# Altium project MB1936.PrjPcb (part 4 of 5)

## Sheet USB_PCIe.SchDoc: USB_PCIe
size A3; Date: Not used; ApprovedBy: Not used; CheckedBy: Not used; Author: Not used; CompanyName: STMicroelectronics; DrawnBy: Not used; Engineer: Not used; Organization: Not used; Address1: Not used; Address2: Not used; Address3: Not used; Address4: Not used; DocumentNumber: Not used; Revision: Not used; SheetNumber: 11; SheetTotal: 18
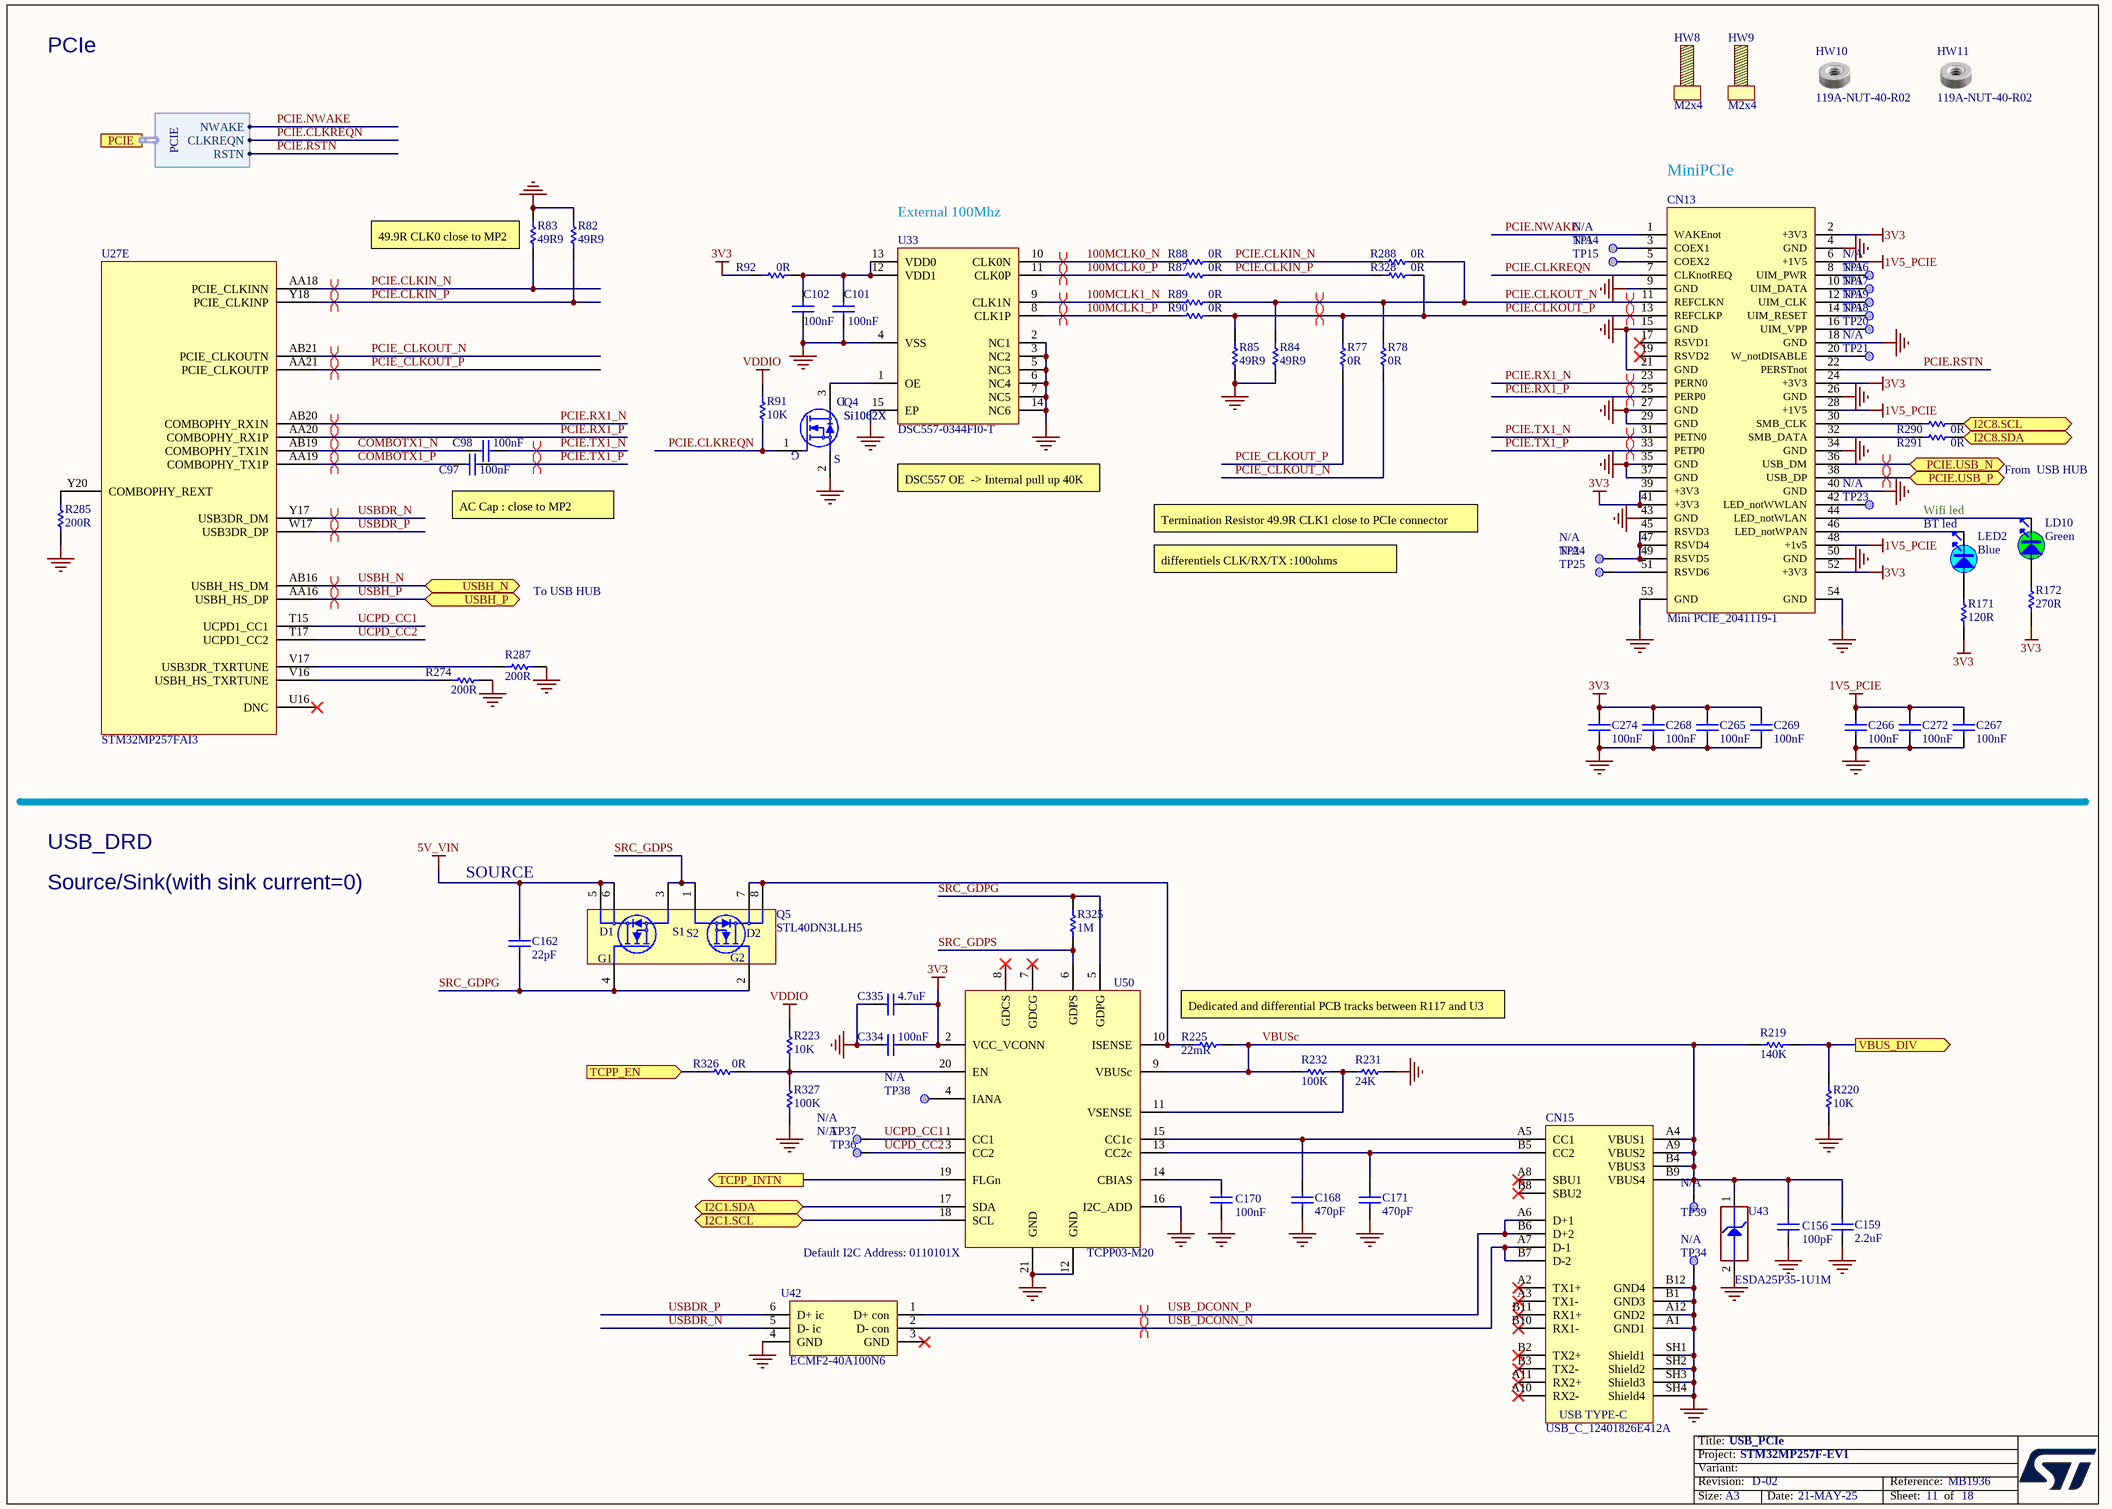
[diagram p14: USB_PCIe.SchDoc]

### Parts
C97  value 100nF  [C0201_MURATA_GRM033_H0P3]  (hidden comment: Capacitor)
C98  value 100nF  [C0201_MURATA_GRM033_H0P3]  (hidden comment: Capacitor)
C101  value 100nF  [C0402]  (hidden comment: Capacitor)
C102  value 100nF  [C0402]  (hidden comment: Capacitor)
C156  value 100pF  [C0402]  (hidden comment: Capacitor)
C159  value 2.2uF  [C0805]  (hidden comment: Capacitor)
C162  value 22pF  [C0402]  (hidden comment: Capacitor)
C168  value 470pF  [C0402]  (hidden comment: Capacitor)
C170  value 100nF  [C0603]  (hidden comment: Capacitor)
C171  value 470pF  [C0402]  (hidden comment: Capacitor)
C265  value 100nF  [C0201_H0P3]  (hidden comment: Capacitor)
C266  value 100nF  [C0201_H0P3]  (hidden comment: Capacitor)
C267  value 100nF  [C0201_H0P3]  (hidden comment: Capacitor)
C268  value 100nF  [C0201_H0P3]  (hidden comment: Capacitor)
C269  value 100nF  [C0201_H0P3]  (hidden comment: Capacitor)
C272  value 100nF  [C0201_H0P3]  (hidden comment: Capacitor)
C274  value 100nF  [C0201_H0P3]  (hidden comment: Capacitor)
C334  value 100nF  [C0402]  (hidden comment: Capacitor)
C335  value 4.7uF  [C0402]  (hidden comment: Capacitor)
CN13  value Mini PCIE_2041119-1  [CON_TE-CONNECTIVITY_2041119-1_HALF-CARD]  (hidden comment: SOCKET_Mini_PCIE)
CN15  value USB_C_12401826E412A  [CON_USB-TYPEC_AMPHENOL_12401826E412A]  (hidden comment: USB_TYPE_C_Receptacle)
HW8  value M2x4  (hidden comment: SCREW)  (mechanical)
HW9  value M2x4  (hidden comment: SCREW)  (mechanical)
HW10  value 119A-NUT-40-R02  [MISC_119A-NUT-40-R02]  (hidden comment: Standoff_mini_PCIE)  (mechanical)
HW11  value 119A-NUT-40-R02  [MISC_119A-NUT-40-R02]  (hidden comment: Standoff_mini_PCIE)  (mechanical)
LD10  value Green  [LED_0603_OSRAM_LG-Q396-PS-35_GREEN_1A2K_H0P4]  (hidden comment: LED_green)
LED2  value Blue  [LED_0603_SMD-B_BLUE_H0P4]  (hidden comment: LED_blue)
Q4  value Si1062X  Manufacturer_Part_Number: Si1062X  [MOS_SC89-3L]  (hidden comment: MOSFET_N-CHANNEL)
Q5  STL40DN3LLH5  [PowerFLAT_5x6]
R77  value 0R  [R0402]  (hidden comment: Resistor)
R78  value 0R  [R0402]  (hidden comment: Resistor)
R82  value 49R9  [R0402]  (hidden comment: Resistor)
R83  value 49R9  [R0402]  (hidden comment: Resistor)
R84  value 49R9  [R0402]  (hidden comment: Resistor)
R85  value 49R9  [R0402]  (hidden comment: Resistor)
R87  value 0R  [R0402]  (hidden comment: Resistor)
R88  value 0R  [R0402]  (hidden comment: Resistor)
R89  value 0R  [R0402]  (hidden comment: Resistor)
R90  value 0R  [R0402]  (hidden comment: Resistor)
R91  value 10K  [R0402]  (hidden comment: Resistor)
R92  value 0R  [R0402]  (hidden comment: Resistor)
R171  value 120R  [R0402]
R172  value 270R  [R0402]  (hidden comment: Resistor)
R219  value 140K  [R0402]  (hidden comment: Resistor)
R220  value 10K  [R0402]  (hidden comment: Resistor)
R223  value 10K  [R0402]  (hidden comment: Resistor)
R225  value 22mR  [R0603]  (hidden comment: Resistor)
R231  value 24K  [R0402]  (hidden comment: Resistor)
R232  value 100K  [R0402]  (hidden comment: Resistor)
R274  value 200R  [R0402]  (hidden comment: Resistor)
R285  value 200R  [R0402]  (hidden comment: Resistor)
R287  value 200R  [R0402]  (hidden comment: Resistor)
R288  value 0R  [R0402]  (hidden comment: Resistor)
R290  value 0R  [R0402]  (hidden comment: Resistor)
R291  value 0R  [R0402]  (hidden comment: Resistor)
R325  value 1M  [R0402]  (hidden comment: Resistor)
R326  value 0R  [R0402]  (hidden comment: Resistor)
R327  value 100K  [R0402]  (hidden comment: Resistor)
R328  value 0R  [R0402]  (hidden comment: Resistor)
TP14  Test Point  [TP_SMD_1MM]  (value not drawn)  (no BOM)
TP15  Test Point  [TP_SMD_1MM]  (value not drawn)  (no BOM)
TP16  Test Point  [TP_SMD_1MM]  (value not drawn)  (no BOM)
TP17  Test Point  [TP_SMD_1MM]  (value not drawn)  (no BOM)
TP18  Test Point  [TP_SMD_1MM]  (value not drawn)  (no BOM)
TP19  Test Point  [TP_SMD_1MM]  (value not drawn)  (no BOM)
TP20  Test Point  [TP_SMD_1MM]  (value not drawn)  (no BOM)
TP21  Test Point  [TP_SMD_1MM]  (value not drawn)  (no BOM)
TP23  Test Point  [TP_SMD_1MM]  (value not drawn)  (no BOM)
TP24  Test Point  [TP_SMD_1MM]  (value not drawn)  (no BOM)
TP25  Test Point  [TP_SMD_1MM]  (value not drawn)  (no BOM)
TP34  Test Point  [TP_SMD_1MM]  (value not drawn)  (no BOM)
TP36  Test Point  [TP_SMD_1MM]  (value not drawn)  (no BOM)
TP37  Test Point  [TP_SMD_1MM]  (value not drawn)  (no BOM)
TP38  Test Point  [TP_SMD_1MM]  (value not drawn)  (no BOM)
TP39  Test Point  [TP_SMD_1MM]  (value not drawn)  (no BOM)
U27  STM32MP257FAI3  [ICC_LFBGA436_18X18_P080_H1P70_STM32MP257_CODE-B0D1]  (part E of 9)
U33  DSC557-0344FI0-T  [ICC_QFN14-EPAD_3P2X2P5_P050]
U42  ECMF2-40A100N6  [ESD_UQFN-6L_1P45X1P4_P040]
U43  value ESDA25P35-1U1M  [ESD_QFN1610_2N_1K_2A]  (hidden comment: ESD-TRANSIL)
U50  TCPP03-M20  [ICC_QFN20-EPAD_4X4_P050]

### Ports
I2C1.SCL (bidir), I2C1.SDA (bidir), I2C8.SCL (bidir), I2C8.SDA (bidir), PCIE (harness PCIE), PCIE.USB_N (bidir), PCIE.USB_P (bidir), TCPP_EN (in), TCPP_INTN (out), USBH_N (bidir), USBH_P (bidir), VBUS_DIV (out)

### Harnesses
PCIE: NWAKE, CLKREQN, RSTN

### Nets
1V5_PCIE: C266.1 C267.1 C272.1 CN13.6(+1V5) CN13.28(+1V5) CN13.48(+1v5)
3V3: C265.1 C268.1 C269.2 C274.1 C334.1 C335.1 CN13.2(+3V3) CN13.24(+3V3) CN13.39(+3V3) CN13.41(+3V3) CN13.52(+3V3) R92.1 R171.2 R172.1 U50.2(VCC_VCONN)
5V_VIN: C162.2 Q5.5(D1) Q5.6(D1)
GND: C101.1 C102.1 C156.1 C159.1 C168.1 C170.1 C171.1 C265.2 C266.2 C267.2 C268.2 C269.1 C272.2 C274.2 C334.2 C335.2 CN13.4(GND) CN13.9(GND) CN13.15(GND) CN13.18(GND) CN13.21(GND) CN13.26(GND) CN13.27(GND) CN13.29(GND) CN13.34(GND) CN13.35(GND) CN13.37(GND) CN13.40(GND) CN13.43(GND) CN13.50(GND) CN13.53(GND) CN13.54(GND) CN15.A1(GND1) CN15.A12(GND2) CN15.B1(GND3) CN15.B12(GND4) CN15.SH1(Shield1) CN15.SH2(Shield2) CN15.SH3(Shield3) CN15.SH4(Shield4) Q4.2(S) R82.2 R83.2 R84.1 R85.1 R220.1 R231.2 R274.2 R285.1 R287.2 R327.1 TP34.1 U33.2(NC1) U33.3(NC2) U33.4(VSS) U33.5(NC3) U33.6(NC4) U33.7(NC5) U33.14(NC6) U33.15(EP) U42.4(GND) U43.2(GND) U50.12(GND) U50.16(I2C_ADD) U50.21(GND)
VDDIO: R91.2 R223.2
100MCLK0_N: R88.1 U33.10(CLK0N)
100MCLK0_P: R87.1 U33.11(CLK0P)
100MCLK1_N: R89.1 U33.9(CLK1N)
100MCLK1_P: R90.1 U33.8(CLK1P)
COMBOTX1_N: C98.1 U27.AB19(COMBOPHY_TX1N)
COMBOTX1_P: C97.1 U27.AA19(COMBOPHY_TX1P)
EXP_GPIO2: R291.2 ; port I2C8.SDA
EXP_GPIO3: R290.2 ; port I2C8.SCL
I2C1.SCL: U50.18(SCL) ; port I2C1.SCL
I2C1.SDA: U50.17(SDA) ; port I2C1.SDA
PCIE.CLKIN_N: R83.1 R88.2 R288.2 U27.AA18(PCIE_CLKINN)
PCIE.CLKIN_P: R82.1 R87.2 R328.2 U27.Y18(PCIE_CLKINP)
PCIE.CLKOUT_N: CN13.11(REFCLKN) R78.2 R84.2 R89.2 R288.1
PCIE.CLKOUT_P: CN13.13(REFCLKP) R77.2 R85.2 R90.2 R328.1
PCIE.CLKREQN: CN13.7(CLKnotREQ) Q4.1(G) R91.1 ; port PCIE.CLKREQN
PCIE.NWAKE: CN13.1(WAKEnot) ; port PCIE.NWAKE
PCIE.RSTN: CN13.22(PERSTnot) ; port PCIE.RSTN
PCIE.RX1_N: CN13.23(PERN0) U27.AB20(COMBOPHY_RX1N)
PCIE.RX1_P: CN13.25(PERP0) U27.AA20(COMBOPHY_RX1P)
PCIE.TX1_N: C98.2 CN13.31(PETN0)
PCIE.TX1_P: C97.2 CN13.33(PETP0)
PCIE.USB_N: CN13.36(USB_DM) ; port PCIE.USB_N
PCIE.USB_P: CN13.38(USB_DP) ; port PCIE.USB_P
PCIE_CLKOUT_N: R78.1 U27.AB21(PCIE_CLKOUTN)
PCIE_CLKOUT_P: R77.1 U27.AA21(PCIE_CLKOUTP)
SRC_GDPG: C162.1 Q5.2(G2) Q5.4(G1) R325.2 U50.5(GDPG)
SRC_GDPS: Q5.1(S2) Q5.3(S1) R325.1 U50.6(GDPS)
TCPP_EN: R326.1 ; port TCPP_EN
TCPP_INTN: U50.19(FLGn) ; port TCPP_INTN
UCPD_CC1: TP37.1 U27.T15(UCPD1_CC1) U50.1(CC1)
UCPD_CC2: TP36.1 U27.T17(UCPD1_CC2) U50.3(CC2)
USB_DCONN_N: CN15.A7(D-1) CN15.B7(D-2) U42.2(D-_con)
USB_DCONN_P: CN15.A6(D+1) CN15.B6(D+2) U42.1(D+_con)
USBDR_N: U27.Y17(USB3DR_DM) U42.5(D-_ic)
USBDR_P: U27.W17(USB3DR_DP) U42.6(D+_ic)
USBH_N: U27.AB16(USBH_HS_DM) ; port USBH_N
USBH_P: U27.AA16(USBH_HS_DP) ; port USBH_P
VBUS_DIV: R219.1 R220.2 ; port VBUS_DIV
VBUSc: C156.2 C159.2 CN15.A4(VBUS1) CN15.A9(VBUS2) CN15.B4(VBUS3) CN15.B9(VBUS4) R219.2 R225.1 R232.1 TP39.1 U43.1(IO1) U50.9(VBUSc)
NetC101_2: C101.2 C102.2 R92.2 U33.12(VDD1) U33.13(VDD0)
NetC168_2: C168.2 CN15.A5(CC1) U50.15(CC1c)
NetC170_2: C170.2 U50.14(CBIAS)
NetC171_2: C171.2 CN15.B5(CC2) U50.13(CC2c)
NetCN13_3: CN13.3(COEX1) TP14.1
NetCN13_5: CN13.5(COEX2) TP15.1
NetCN13_8: CN13.8(UIM_PWR) TP16.1
NetCN13_10: CN13.10(UIM_DATA) TP17.1
NetCN13_12: CN13.12(UIM_CLK) TP19.1
NetCN13_14: CN13.14(UIM_RESET) TP18.1
NetCN13_16: CN13.16(UIM_VPP) TP20.1
NetCN13_20: CN13.20(W_notDISABLE) TP21.1
NetCN13_30: CN13.30(SMB_CLK) R290.1
NetCN13_32: CN13.32(SMB_DATA) R291.1
NetCN13_42: CN13.42(LED_notWWLAN) TP23.1
NetCN13_44: CN13.44(LED_notWLAN) LD10.2
NetCN13_45: CN13.45(RSVD3) CN13.47(RSVD4) CN13.49(RSVD5) TP24.1
NetCN13_46: CN13.46(LED_notWPAN) LED2.2
NetCN13_51: CN13.51(RSVD6) TP25.1
NetLD10_1: LD10.1 R172.2
NetLED2_1: LED2.1 R171.1
NetQ4_3: Q4.3(D) U33.1(OE)
NetQ5_7: Q5.7(D2) Q5.8(D2) R225.2 U50.10(ISENSE)
NetR223_1: R223.1 R326.2 R327.2 U50.20(EN)
NetR231_1: R231.1 R232.2 U50.11(VSENSE)
NetR274_1: R274.1 U27.V16(USBH_HS_TXRTUNE)
NetR285_2: R285.2 U27.Y20(COMBOPHY_REXT)
NetR287_1: R287.1 U27.V17(USB3DR_TXRTUNE)
NetTP38_1: TP38.1 U50.4(IANA)

Not connected (* = marked no-connect by the designer): CN13 17(RSVD1)* 19(RSVD2)*; CN15 A2(TX1+)* A3(TX1-)* A8(SBU1)* A10(RX2-)* A11(RX2+)* B2(TX2+)* B3(TX2-)* B8(SBU2)* B10(RX1-)* B11(RX1+)*; U27 U16(DNC)*; U42 3(GND)*; U50 7(GDCG)* 8(GDCS)*

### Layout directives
differential pair: 100MCLK0_N, 100MCLK0_P, 100MCLK1_N, 100MCLK1_P, COMBOTX1_N, COMBOTX1_P, PCIE.CLKIN_N, PCIE.CLKIN_P, PCIE.CLKOUT_N, PCIE.CLKOUT_P, PCIE.RX1_N, PCIE.RX1_P, PCIE.TX1_N, PCIE.TX1_P, PCIE.USB_N, PCIE.USB_P, PCIE_CLKOUT_N, PCIE_CLKOUT_P, USB_DCONN_N, USB_DCONN_P, USBDR_N, USBDR_P, USBH_N, USBH_P

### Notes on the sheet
- PCIe
- MiniPCIe
- (near R83) 49.9R CLK0 close to MP2
- (near U33) External 100Mhz
- AC Cap : close to MP2
- DSC557 OE  -> Internal pull up 40K
- (near LED2) Wifi led
- From  USB HUB
- differentiels CLK/RX/TX :100ohms
- Termination Resistor 49.9R CLK1 close to PCIe connector
- (near LED2) BT led
- To USB HUB
- USB_DRD
- Source/Sink(with sink current=0)
- SOURCE
- Dedicated and differential PCB tracks between R117 and U3 pin 9 and 10
- (near U50) Default I2C Address: 0110101X

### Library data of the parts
C97 C98 = MCD-01535: Capacitor, MLCC,100nF, 10V, X7R, +/-10%, 0201, T=0.3mm; Part_Preference: Recommended; Manufacturer: MURATA; Manufacturer_Part_Number: GRM033R61A104KE15; Order_Code_RS: 790-2742; Component_Country_Of_Origin: Japan°°; ID: 3635; ShowFields: YES
C101 C102 C334 = MCD-00006: Capacitor, MLCC, 100nF, 16V, X7R, +/-10%, 0402, T=0.5mm; Part_Preference: Recommended; Manufacturer: YAGEO; Manufacturer_Part_Number: CC0402KRX7R7BB104; Partial_Alternate_Internal_Part_Number: MCD-03299; Order_Code_RS: 9402047; Component_Country_Of_Origin: China; ID: 2474; ShowFields: YES
C156 = MCD-00205: Capacitor, MLCC, 100pF, 50V, NPO, +/-5%, 0402, T=0.5mm; Manufacturer_Part_Number: CC0402JRNPO9BN101; Manufacturer: YAGEO; Part_Preference: Recommended; Component_Country_Of_Origin: China; ID: 2658; ShowFields: YES
C159 = MCD-02372: Capacitor, MLCC, 2.2uF, 25V, X7R, +/-10%, 0805, T=1,25mm; Part_Preference: Recommended; Manufacturer: MURATA; Manufacturer_Part_Number: GRM21BR71E225KE11; Partial_Alternate_Internal_Part_Number: MCD-04185; Component_Country_Of_Origin: Japan°; ID: 4478; ShowFields: YES
C162 = MCD-01995: Capacitor, MLCC, 22pF, 50V, C0G, +/-5%, 0402, T=0.5mm; Part_Preference: Recommended; Manufacturer: TDK; Manufacturer_Part_Number: C1005NP01H220J050BA; Partial_Alternate_Internal_Part_Number: MCD-04601; Component_Country_Of_Origin: Unknown; ID: 4095; ShowFields: YES
C168 C171 = MCD-00724: Capacitor, MLCC, 470pF, 50V, NPO, +/-5%, 0402, T=0.5mm; Manufacturer_Part_Number: CC0402JRNPO9BN471; Manufacturer: YAGEO; Part_Preference: Recommended; Component_Country_Of_Origin: China; Order_Code_RS: 199-2186; ID: 3023; ShowFields: YES
C170 = MCD-01099: Capacitor, MLCC, 100nF, 50V, X7R, +/-10%, 0603, T=0.8mm; BMS_Part_Number: 9142278; Part_Preference: Recommended; Manufacturer: YAGEO; Manufacturer_Part_Number: CC0603KRX7R9BB104; Order_Code_RS: 669-8767; Component_Country_Of_Origin: China; ID: 3397; ShowFields: YES
C265-C269 C272 C274 = MCD-00697: Capacitor, MLCC, 100nF,10V, X5R, +/-10%, 0201, T=0.3mm; Manufacturer_Part_Number: C0603X5R1A104K030BC; Manufacturer: TDK; Part_Preference: Recommended; Component_Country_Of_Origin: Unknown; ID: 3046; ShowFields: YES
C335 = MCD-01356: Capacitor, MLCC, 4.7uF, 6V3, X5R, +/-20%, 0402, T=0.5mm; Part_Preference: Recommended; Manufacturer: MURATA; Manufacturer_Part_Number: GRM155R60J475ME47; Partial_Alternate_Internal_Part_Number: MCD-04455; Order_Code_RS: 814-5230; Component_Country_Of_Origin: Japan°°; ID: 3456; ShowFields: YES
CN13 = MCD-02227: Socket_Mini PCIE, 52 pins, RA, SMD, T=4mm; Part_Type: Connector; Part_Preference: Recommended; Manufacturer: TE CONNECTIVITY; Manufacturer_Part_Number: 2041119-1; Order_Code_RS: 186-5008; Component_Country_Of_Origin: China; ShowFields: YES; ID: 4327
CN15 = MCD-03232: USB_TypeC, 24 pins, RA, SMD, T=2.96mm; Part_Type: Connector; Part_Preference: Recommended; Manufacturer: AMPHENOL CS; Manufacturer_Part_Number: 12401826E412A; Component_Country_Of_Origin: China°; ShowFields: YES; ID: 5348
HW8 HW9 = MCD-02934: Screw , M2*4 mm; Part_Type: Accessory; Part_Preference: Recommended; Manufacturer: RS PRO; Manufacturer_Part_Number: 914-1462; ShowFields: YES; ID: 5050; Component_Country_Of_Origin: Vietnam
HW10 HW11 = MCD-03022: MiniPCIe Stand off , 1.6mm; Part_Type: Mechanical; Part_Preference: Recommended; Manufacturer: ATTEND; ShowFields: YES; ID: 5138; Component_Country_Of_Origin: Taiwan
LD10 = MCD-02901: LED, Green, 2V, 20mA, 0603; Part_Type: Display; Part_Preference: Recommended; Manufacturer: EVERLIGHT; Manufacturer_Part_Number: 19-217/G7C-AN1P2/6T; Partial_Alternate_Internal_Part_Number: MCD-02400, MCD-00588; Component_Country_Of_Origin: China; ShowFields: YES; ID: 5017
LED2 = MCD-02786: LED, Blue, 2.5V to 3.1V, 10mA, 0603; Part_Type: Display; Part_Preference: Recommended; Manufacturer: EVERLIGHT; Manufacturer_Part_Number: 19-217/BHC-ZL1M2RY/6T; Full_Alternate_Internal_Part_Number: MCD-01131; Component_Country_Of_Origin: China; ShowFields: YES; ID: 4898
Q4 = MCD-02221: MOSFET N-CH 20V SC-89; Part_Preference: Recommended; Part_Type: Transistor; Manufacturer: VISHAY; Order_Code_RS: 812-3044; Component_Country_Of_Origin: Philippines; ID: 4321; ShowFields: YES
Q5 = MCD-02152: MOSFET, Dual N-channel 30 V, 0.016 Ω typ., 40 A, STripFET™ H5 Power MOSFET; Part_Preference: Recommended; Part_Type: Transistor; Manufacturer: STMICROELECTRONICS; Manufacturer_HQ_COO: EU; Component_Country_Of_Origin: China; ID: 4252; ShowFields: YES
R77 R78 R87-R90 R92 = MCD-00052: Resistor, 0R, 0402, +/-5%, 1/16W; Part_Preference: Recommended; Manufacturer: YAGEO; Manufacturer_Part_Number: RC0402JR-070RL; Order_Code_RS: 9232516RL; Component_Country_Of_Origin: China; ID: 2540; ShowFields: YES
R82-R85 = MCD-00565: Resistor, 49R9, 0402, +/-1%, 1/16W; Part_Preference: Recommended; Manufacturer: YAGEO; Manufacturer_Part_Number: RC0402FR-0749R9L; Component_Country_Of_Origin: China; ID: 3178; ShowFields: YES
R91 R220 R223 = MCD-00053: Resistor, 10K, 0402, +/-1%, 1/16W; BMS_Part_Number: 9131590; Part_Preference: Recommended; Manufacturer: YAGEO; Manufacturer_Part_Number: RC0402FR-0710KL; Order_Code_RS: 9239359; Component_Country_Of_Origin: China; ID: 2539; ShowFields: YES
R171 = MCD-00194: Resistor,120R,0402,1%,1/16W; Manufacturer_Part_Number: RC0402FR-07120RL; Manufacturer: YAGEO; Part_Preference: Recommended; Provided_By: SUBCO; ECCN_US: EAR99; ECCN_EU: NEC; Component_Country_Of_Origin: China; ID: 2674; ShowFields: YES
R172 = MCD-00441: Resistor,270R,0402,1%,1/16W; Manufacturer_Part_Number: RC0402FR-07270RL; Manufacturer: YAGEO; Part_Preference: Recommended; Provided_By: SUBCO; ECCN_US: EAR99; ECCN_EU: NEC; Component_Country_Of_Origin: China; ID: 2838; ShowFields: YES
R219 = MCD-02335: Resistor, 140K, 0402, +/-1%, 1/16W; Part_Preference: Recommended; Manufacturer: YAGEO; Manufacturer_Part_Number: RC0402FR-07140KL; Component_Country_Of_Origin: China; ID: 4441; ShowFields: YES
R225 = MCD-02232: Resistor, 22mR, 0603, +/-1%, 1/3W; Part_Preference: Recommended; Manufacturer: PANASONIC; Manufacturer_Part_Number: ERJ-3BWFR022V; Order_Code_RS: 763-8671P; Component_Country_Of_Origin: Japan; ID: 4332; ShowFields: YES
R231 = MCD-00435: Resistor, 24K, 0402, +/-1%, 1/16W; Part_Preference: Recommended; Manufacturer: YAGEO; Manufacturer_Part_Number: RC0402FR-0724KL; Component_Country_Of_Origin: China; ShowFields: YES; ID: 2845
R232 R327 = MCD-02265: Resistor,100K,0402,0.5%,1/16W; Part_Preference: Recommended; Manufacturer: YAGEO; Manufacturer_Part_Number: RC0402DR-07100KL; Component_Country_Of_Origin: China; ShowFields: YES; ID: 4365
R274 R285 R287 = MCD-00417: Resistor, 200R, 0402, +/-1%, 1/16W; Part_Preference: Recommended; Manufacturer: YAGEO; Manufacturer_Part_Number: RC0402FR-07200RL; Component_Country_Of_Origin: China; ID: 2860; ShowFields: YES
R288 R328 = MCD-00052: Resistor,0R,0402,5%,1/16W; Part_Preference: Recommended; Manufacturer: YAGEO; Manufacturer_Part_Number: RC0402JR-070RL; Order_Code_RS: 9232516RL; Component_Country_Of_Origin: China; ID: 2540; ShowFields: YES
R290 R291 = MCD-00052: Resistor, 0R, 0402, +/-5%, 1/16W; Part_Preference: Recommended; Manufacturer: YAGEO; Manufacturer_Part_Number: RC0402JR-070RL; Order_Code_RS: 9232516RL; Component_Country_Of_Origin: China; ShowFields: YES; ID: 2540
R325 = MCD-00182: Resistor, 1M, 0402, +/-1%, 1/16W; BMS_Part_Number: 9131778; Part_Preference: Recommended; Manufacturer: YAGEO; Manufacturer_Part_Number: RC0402FR-071ML; Order_Code_RS: 618-6194; Component_Country_Of_Origin: China; ShowFields: YES; ID: 2686
R326 = MCD-00052: Resistor,0R,0402,5%,1/16W; Manufacturer_Part_Number: RC0402JR-070RL; Manufacturer: YAGEO; Part_Preference: Recommended; Order_Code_RS: 9232516RL; Component_Country_Of_Origin: China; ID: 2540; ShowFields: YES
TP14-TP21 TP23-TP25 TP34 TP36-TP39 = MCD-00074: Test Point 1mm; Part_Type: Misc; Part_Preference: Recommended; Component_Country_Of_Origin: Unknown; ID: 2518; ShowFields: YES
U27 = MCD-02000: MPU, ARM Cortex-A35 + M33 32-bit MPU, 808KB RAM, With Crypto; Part_Type: IC; Part_Preference: Recommended; Manufacturer: STMICROELECTRONICS; Manufacturer_HQ_COO: EU; Component_Country_Of_Origin: Unknown; ShowFields: YES; ID: 4100
U33 = MCD-02349: Crystal-less Two Output PCIe Gen1/2/3 Clock Generator 100Mhz , 2.25V to 3.6V, 100ppm; Part_Type: IC; Part_Preference: Recommended; Manufacturer: MICROCHIP; Component_Country_Of_Origin: Unknown; ID: 4455; ShowFields: YES
U42 = MCD-03060: ESD protection & Common Filter High Speed serial Interfaces , 0.4 pitch; Part_Type: IC; Part_Preference: Recommended; Manufacturer: STMICROELECTRONICS; ShowFields: YES; ID: 5176; Component_Country_Of_Origin: China
U43 = MCD-01207: High power Transient voltage suppressor:25V/35A EOS and ESD transients protection.; BMS_Part_Number: 9179045; Part_Type: Diode; Part_Preference: Recommended; Manufacturer: STMICROELECTRONICS; Manufacturer_HQ_COO: EU; Component_Country_Of_Origin: China; Order_Code_RS: 163-9774; ID: 3289; ShowFields: YES
U50 = MCD-02130: USB Type-C Port Protection for USB DRP Power Delivery, PPS compliant; Part_Preference: Recommended; Part_Type: IC; Manufacturer: STMICROELECTRONICS; Manufacturer_HQ_COO: EU; Component_Country_Of_Origin: China; ID: 4230; ShowFields: YES

## Sheet STLINK_V3EC.SchDoc: STLINK-V3EC
size A3; Date: Not used; ApprovedBy: Not used; CheckedBy: Not used; Author: Not used; CompanyName: STMicroelectronics; DrawnBy: Not used; Engineer: Not used; Organization: Not used; Address1: Not used; Address2: Not used; Address3: Not used; Address4: Not used; DocumentNumber: Not used; Revision: V0.1; SheetNumber: 18; SheetTotal: 18
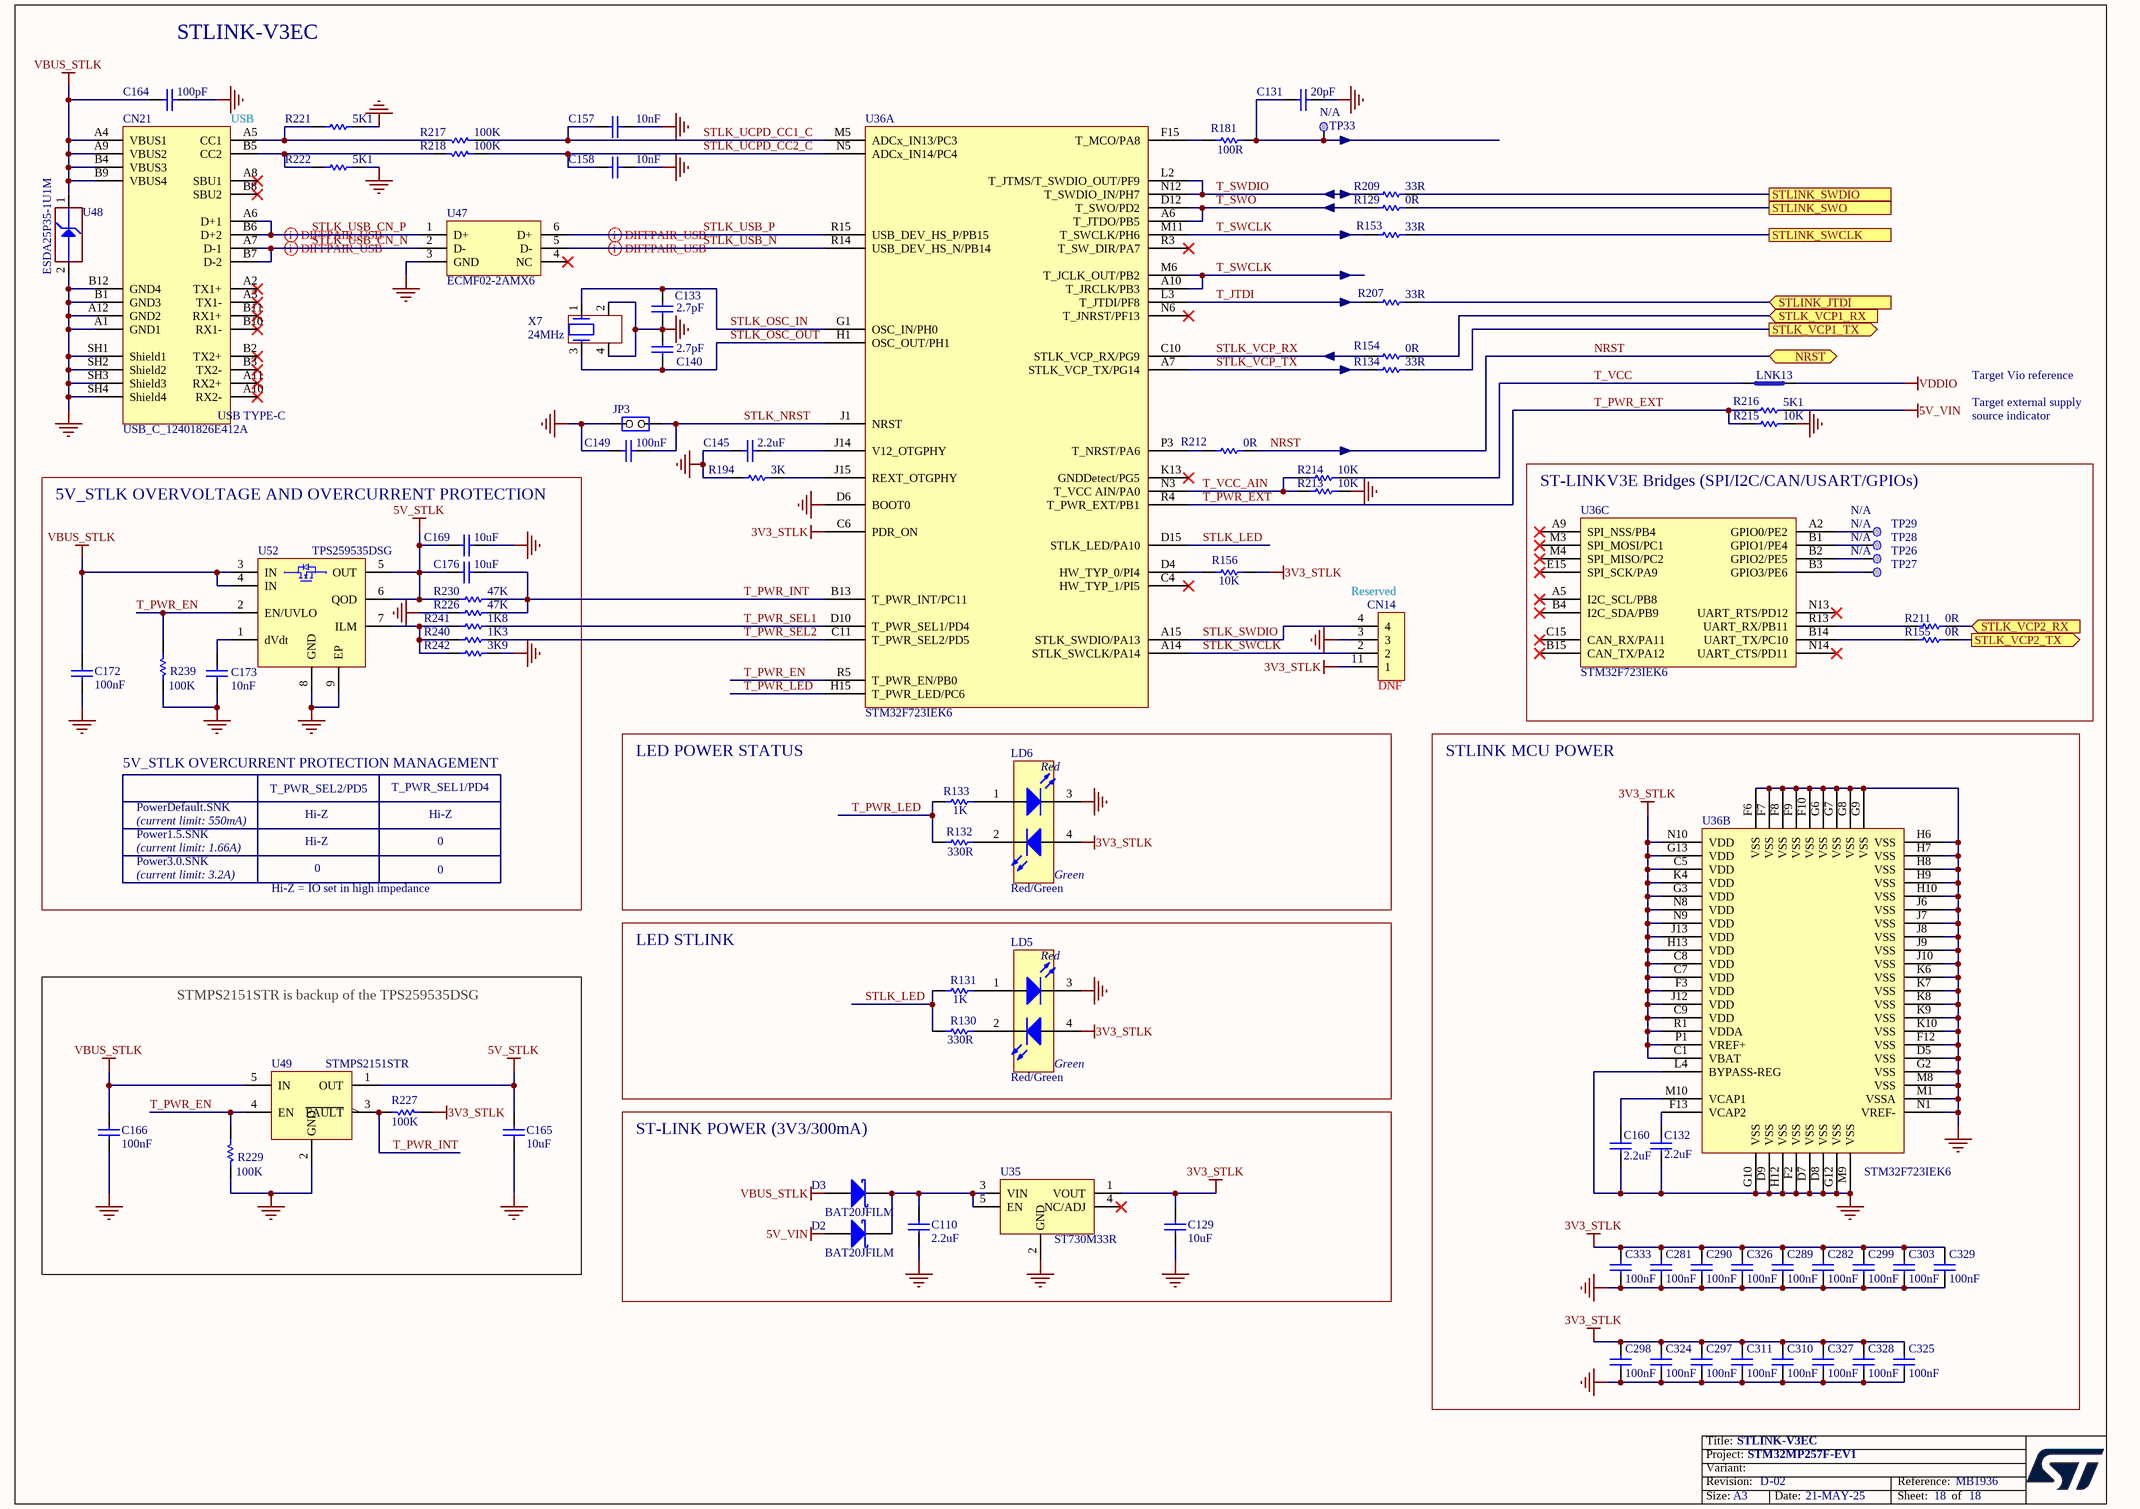
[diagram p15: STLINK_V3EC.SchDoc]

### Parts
C110  value 2.2uF  [C0805]  (hidden comment: Capacitor)
C129  value 10uF  [C0603]  (hidden comment: Capacitor)
C131  value 20pF  [C0402]  (hidden comment: Capacitor)
C132  value 2.2uF  [C0402]  (hidden comment: Capacitor)
C133  value 2.7pF  [C0402]  (hidden comment: Capacitor)
C140  value 2.7pF  [C0402]  (hidden comment: Capacitor)
C145  value 2.2uF  [C0402]  (hidden comment: Capacitor)
C149  value 100nF  [C0402]  (hidden comment: Capacitor)
C157  value 10nF  [C0402]  (hidden comment: Capacitor)
C158  value 10nF  [C0402]  (hidden comment: Capacitor)
C160  value 2.2uF  [C0402]  (hidden comment: Capacitor)
C164  value 100pF  [C0402]  (hidden comment: Capacitor)
C165  value 10uF  [C0603]  (hidden comment: Capacitor)
C166  value 100nF  [C0402]  (hidden comment: Capacitor)
C169  value 10uF  [C0603]  (hidden comment: Capacitor)
C172  value 100nF  [C0402]  (hidden comment: Capacitor)
C173  value 10nF  [C0402]  (hidden comment: Capacitor)
C176  value 10uF  [C0402]  (hidden comment: Capacitor)
C281  value 100nF  [C0402]  (hidden comment: Capacitor)
C282  value 100nF  [C0402]  (hidden comment: Capacitor)
C289  value 100nF  [C0402]  (hidden comment: Capacitor)
C290  value 100nF  [C0402]  (hidden comment: Capacitor)
C297  value 100nF  [C0402]  (hidden comment: Capacitor)
C298  value 100nF  [C0402]  (hidden comment: Capacitor)
C299  value 100nF  [C0402]  (hidden comment: Capacitor)
C303  value 100nF  [C0402]  (hidden comment: Capacitor)
C310  value 100nF  [C0402]  (hidden comment: Capacitor)
C311  value 100nF  [C0402]  (hidden comment: Capacitor)
C324  value 100nF  [C0402]  (hidden comment: Capacitor)
C325  value 100nF  [C0402]  (hidden comment: Capacitor)
C326  value 100nF  [C0402]  (hidden comment: Capacitor)
C327  value 100nF  [C0402]  (hidden comment: Capacitor)
C328  value 100nF  [C0402]  (hidden comment: Capacitor)
C329  value 100nF  [C0402]  (hidden comment: Capacitor)
C333  value 100nF  [C0402]  (hidden comment: Capacitor)
CN14  Header 4x1  [CON_SAMTEC_TSW-104-07-G-S]  (value not drawn)
CN21  value USB_C_12401826E412A  [CON_USB-TYPEC_AMPHENOL_12401826E412A]  (hidden comment: USB_TYPE_C_Receptacle)
D2  value BAT20JFILM  [DIO_SOD323_1A_2K]  (hidden comment: SCHOTTKY_1A_2K)
D3  value BAT20JFILM  [DIO_SOD323_1A_2K]  (hidden comment: SCHOTTKY_1A_2K)
JP3  Jumper_Header 2x1  [CON_SAMTEC_TSW-102-07-G-S]  (value not drawn)
LD5  value Red/Green  [LED_BI-GR_WE-150141SV73110]  (hidden comment: LED_BICOLOR)
LD6  value Red/Green  [LED_BI-GR_WE-150141SV73110]  (hidden comment: LED_BICOLOR)
LNK13  link_200  [LINK200]  (value not drawn)  (no BOM)
R129  value 0R  [R0402]  (hidden comment: Resistor)
R130  value 330R  [R0402]  (hidden comment: Resistor)
R131  value 1K  [R0402]  (hidden comment: Resistor)
R132  value 330R  [R0402]  (hidden comment: Resistor)
R133  value 1K  [R0402]  (hidden comment: Resistor)
R134  value 33R  [R0402]  (hidden comment: Resistor)
R153  value 33R  [R0402]  (hidden comment: Resistor)
R154  value 0R  [R0402]  (hidden comment: Resistor)
R155  value 0R  [R0402]  (hidden comment: Resistor)
R156  value 10K  [R0402]  (hidden comment: Resistor)
R181  value 100R  [R0402]  (hidden comment: Resistor)
R194  value 3K  [R0402]  (hidden comment: Resistor)
R207  value 33R  [R0402]  (hidden comment: Resistor)
R209  value 33R  [R0402]  (hidden comment: Resistor)
R211  value 0R  [R0402]  (hidden comment: Resistor)
R212  value 0R  [R0402]  (hidden comment: Resistor)
R213  value 10K  [R0402]  (hidden comment: Resistor)
R214  value 10K  [R0402]  (hidden comment: Resistor)
R215  value 10K  [R0402]  (hidden comment: Resistor)
R216  value 5K1  [R0402]  (hidden comment: Resistor)
R217  value 100K  [R0402]  (hidden comment: Resistor)
R218  value 100K  [R0402]  (hidden comment: Resistor)
R221  value 5K1  [R0402]  (hidden comment: Resistor)
R222  value 5K1  [R0402]  (hidden comment: Resistor)
R226  value 47K  [R0402]  (hidden comment: Resistor)
R227  value 100K  [R0402]  (hidden comment: Resistor)
R229  value 100K  [R0402]  (hidden comment: Resistor)
R230  value 47K  [R0402]  (hidden comment: Resistor)
R239  value 100K  [R0402]  (hidden comment: Resistor)
R240  value 1K3  [R0402]  (hidden comment: Resistor)
R241  value 1K8  [R0402]  (hidden comment: Resistor)
R242  value 3K9  [R0402]  (hidden comment: Resistor)
TP26  Test Point  [TP_SMD_1MM]  (value not drawn)  (no BOM)
TP27  Test Point  [TP_SMD_1MM]  (value not drawn)  (no BOM)
TP28  Test Point  [TP_SMD_1MM]  (value not drawn)  (no BOM)
TP29  Test Point  [TP_SMD_1MM]  (value not drawn)  (no BOM)
TP33  Test Point  [TP_SMD_1MM]  (value not drawn)  (no BOM)
U35  ST730M33R  [ICC_SOT23-5L_H1P45]
U36  value STM32F723IEK6  [ICC_UFBGA201_176+25_10X10_P065]  (hidden comment: STLINK-V3EC)  (parts A,B,C of 3)
U47  value ECMF02-2AMX6  [ESD_QFN-6L_1P7X1P5_P050]  (hidden comment: ​)
U48  value ESDA25P35-1U1M  [ESD_QFN1610_2N_1K_2A]  (hidden comment: ESD-TRANSIL)
U49  STMPS2151STR  [MOS_SOT23-5L]
U52  TPS259535DSG  [ICC_WSON8-EPAD_2X2_P050]
X7  value 24MHz  [CRY_NX2016SA_4P]  (hidden comment: XTAL_4_PINS)

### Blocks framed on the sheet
5V_STLK OVERVOLTAGE AND OVERCURRENT PROTECTION: C169 C172 C173 C176 R226 R230 R239-R242 U52
ST-LINKV3E Bridges (SPI/I2C/CAN/USART/GPIOs): R155 R211 TP26-TP29 U36
LED POWER STATUS: LD6 R132 R133
STLINK MCU POWER: C132 C160 C281 C282 C289 C290 C297-C299 C303 C310 C311 C324-C329 C333 U36
LED STLINK: LD5 R130 R131
STMPS2151STR is backup of the TPS259535DSG: C165 C166 R227 R229 U49
ST-LINK POWER (3V3/300mA): C110 C129 D2 D3 U35

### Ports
NRST (bidir), STLINK_JTDI (in), STLINK_SWCLK, STLINK_SWDIO, STLINK_SWO, STLK_VCP1_RX (in), STLK_VCP1_TX (out), STLK_VCP2_RX (in), STLK_VCP2_TX (out)

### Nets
3V3_STLK: C129.2 C281.1 C282.1 C289.1 C290.1 C297.1 C298.1 C299.1 C303.1 C310.1 C311.1 C324.1 C325.1 C326.1 C327.1 C328.1 C329.1 C333.1 CN14.1 LD5.4(Green_anode) LD6.4(Green_anode) R156.2 R227.1 U35.1(VOUT) U36.C1(VBAT) U36.C5(VDD) U36.C6(PDR_ON) U36.C7(VDD) U36.C8(VDD) U36.C9(VDD) U36.F3(VDD) U36.G3(VDD) U36.G13(VDD) U36.H13(VDD) U36.J12(VDD) U36.J13(VDD) U36.K4(VDD) U36.N8(VDD) U36.N9(VDD) U36.N10(VDD) U36.P1(VREF+) U36.R1(VDDA)
5V_STLK: C165.2 C169.2 C176.1 R230.1 U49.1(OUT) U52.5(OUT) U52.6(QOD)
5V_VIN: D2.1(A) R216.2
GND: C110.1 C129.1 C131.1 C132.1 C133.2 C140.1 C145.1 C149.1 C157.2 C158.2 C160.1 C164.2 C165.1 C166.1 C169.1 C172.1 C173.1 C281.2 C282.2 C289.2 C290.2 C297.2 C298.2 C299.2 C303.2 C310.2 C311.2 C324.2 C325.2 C326.2 C327.2 C328.2 C329.2 C333.2 CN14.3 CN21.A1(GND1) CN21.A12(GND2) CN21.B1(GND3) CN21.B12(GND4) CN21.SH1(Shield1) CN21.SH2(Shield2) CN21.SH3(Shield3) CN21.SH4(Shield4) JP3.2(NO) LD5.3(RED_cathode) LD6.3(RED_cathode) R194.2 R213.2 R215.2 R221.2 R222.2 R226.2 R229.1 R239.1 R242.2 U35.2(GND) U36.D5(VSS) U36.D6(BOOT0) U36.D7(VSS) U36.D8(VSS) U36.D9(VSS) U36.F2(VSS) U36.F6(VSS) U36.F7(VSS) U36.F8(VSS) U36.F9(VSS) U36.F10(VSS) U36.F12(VSS) U36.G2(VSS) U36.G6(VSS) U36.G7(VSS) U36.G8(VSS) U36.G9(VSS) U36.G10(VSS) U36.G12(VSS) U36.H6(VSS) U36.H7(VSS) U36.H8(VSS) U36.H9(VSS) U36.H10(VSS) U36.H12(VSS) U36.J6(VSS) U36.J7(VSS) U36.J8(VSS) U36.J9(VSS) U36.J10(VSS) U36.K6(VSS) U36.K7(VSS) U36.K8(VSS) U36.K9(VSS) U36.K10(VSS) U36.L4(BYPASS-REG) U36.M1(VSSA) U36.M8(VSS) U36.M9(VSS) U36.N1(VREF-) U47.3(GND) U48.2(GND) U49.2(GND) U52.8(GND) U52.9(EP) X7.2 X7.4
VBUS_STLK: C164.1 C166.2 C172.2 CN21.A4(VBUS1) CN21.A9(VBUS2) CN21.B4(VBUS3) CN21.B9(VBUS4) D3.1(A) U48.1(IO1) U49.5(IN) U52.3(IN) U52.4(IN)
VDDIO: LNK13.1
JTCK_SWCLK: R153.2 ; port STLINK_SWCLK
JTDI: R207.2 ; port STLINK_JTDI
JTDO_SWDO: R129.2 ; port STLINK_SWO
JTMS_SWDIO: R209.2 ; port STLINK_SWDIO
NRST: R212.2 ; port NRST
STLK_LED: R130.1 R131.2 U36.D15(STLK_LED/PA10)
STLK_NRST: C149.2 JP3.1(COMMON) U36.J1(NRST)
STLK_OSC_IN: C133.1 U36.G1(OSC_IN/PH0) X7.1
STLK_OSC_OUT: C140.2 U36.H1(OSC_OUT/PH1) X7.3
STLK_SWCLK: CN14.2 U36.A14(STLK_SWCLK/PA14)
STLK_SWDIO: CN14.4 U36.A15(STLK_SWDIO/PA13)
STLK_UCPD_CC1_C: C157.1 R217.1 U36.M5(ADCx_IN13/PC3)
STLK_UCPD_CC2_C: C158.1 R218.1 U36.N5(ADCx_IN14/PC4)
STLK_USB_CN_N: CN21.A7(D-1) CN21.B7(D-2) U47.2(D-)
STLK_USB_CN_P: CN21.A6(D+1) CN21.B6(D+2) U47.1(D+)
STLK_USB_N: U36.R14(USB_DEV_HS_N/PB14) U47.5(D-)
STLK_USB_P: U36.R15(USB_DEV_HS_P/PB15) U47.6(D+)
STLK_VCP1_RX: R154.2 ; port STLK_VCP1_RX
STLK_VCP1_TX: R134.2 ; port STLK_VCP1_TX
STLK_VCP2_RX: R211.1 ; port STLK_VCP2_RX
STLK_VCP2_TX: R155.1 ; port STLK_VCP2_TX
STLK_VCP_RX: R154.1 U36.C10(STLK_VCP_RX/PG9)
STLK_VCP_TX: R134.1 U36.A7(STLK_VCP_TX/PG14)
T_JTDI: R207.1 U36.L3(T_JTDI/PF8)
T_PWR_EN: R229.2 R239.2 U36.R5(T_PWR_EN/PB0) U49.4(EN) U52.2(EN/UVLO)
T_PWR_EXT: R215.1 R216.1 U36.R4(T_PWR_EXT/PB1)
T_PWR_INT: C176.2 R226.1 R227.2 R230.2 U36.B13(T_PWR_INT/PC11) U49.3(~{FAULT})
T_PWR_LED: R132.2 R133.2 U36.H15(T_PWR_LED/PC6)
T_PWR_SEL1: R241.2 U36.D10(T_PWR_SEL1/PD4)
T_PWR_SEL2: R240.2 U36.C11(T_PWR_SEL2/PD5)
T_SWCLK: R153.1 U36.A10(T_JRCLK/PB3) U36.M6(T_JCLK_OUT/PB2) U36.M11(T_SWCLK/PH6)
T_SWDIO: R209.1 U36.L2(T_JTMS/T_SWDIO_OUT/PF9) U36.N12(T_SWDIO_IN/PH7)
T_SWO: R129.1 U36.A6(T_JTDO/PB5) U36.D12(T_SWO/PD2)
T_VCC: LNK13.2 R214.2
T_VCC_AIN: R213.1 R214.1 U36.N3(T_VCC_AIN/PA0)
NetC110_2: C110.2 D2.2(K) D3.2(K) U35.3(VIN) U35.5(EN)
NetC131_2: C131.2 R181.2 TP33.1
NetC132_2: C132.2 U36.F13(VCAP2)
NetC145_2: C145.2 U36.J14(V12_OTGPHY)
NetC160_2: C160.2 U36.M10(VCAP1)
NetC173_2: C173.2 U52.1(dVdt)
NetCN21_A5: CN21.A5(CC1) R217.2 R221.1
NetCN21_B5: CN21.B5(CC2) R218.2 R222.1
NetLD5_1: LD5.1(Red_anode) R131.1
NetLD5_2: LD5.2(Green_cathode) R130.2
NetLD6_1: LD6.1(Red_anode) R133.1
NetLD6_2: LD6.2(Green_cathode) R132.1
NetR155_2: R155.2 U36.B14(UART_TX/PC10)
NetR156_1: R156.1 U36.D4(HW_TYP_0/PI4)
NetR181_1: R181.1 U36.F15(T_MCO/PA8)
NetR194_1: R194.1 U36.J15(REXT_OTGPHY)
NetR211_2: R211.2 U36.R13(UART_RX/PB11)
NetR212_1: R212.1 U36.P3(T_NRST/PA6)
NetR240_1: R240.1 R241.1 R242.1 U52.7(ILM)
NetTP26_1: TP26.1 U36.B2(GPIO2/PE5)
NetTP27_1: TP27.1 U36.B3(GPIO3/PE6)
NetTP28_1: TP28.1 U36.B1(GPIO1/PE4)
NetTP29_1: TP29.1 U36.A2(GPIO0/PE2)

Not connected (* = marked no-connect by the designer): CN21 A2(TX1+)* A3(TX1-)* A8(SBU1)* A10(RX2-)* A11(RX2+)* B2(TX2+)* B3(TX2-)* B8(SBU2)* B10(RX1-)* B11(RX1+)*; U35 4(NC/ADJ)*; U36 A5(I2C_SCL/PB8)* A9(SPI_NSS/PB4)* B4(I2C_SDA/PB9)* B15(CAN_TX/PA12)* C4(HW_TYP_1/PI5)* C15(CAN_RX/PA11)* E15(SPI_SCK/PA9)* K13(GNDDetect/PG5)* M3(SPI_MOSI/PC1)* M4(SPI_MISO/PC2)* N6(T_JNRST/PF13)* N13(UART_RTS/PD12)* N14(UART_CTS/PD11)* R3(T_SW_DIR/PA7)*; U47 4(NC)*

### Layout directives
differential pair; rule Impedance Constraint [Min = 85.00    Max = 95.00    ]: STLK_USB_CN_N, STLK_USB_CN_P, STLK_USB_N, STLK_USB_P

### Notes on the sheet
- STLINK-V3EC
- (near CN21) USB
- Target Vio reference
- Target external supply
- source indicator
- (near CN14) Reserved
- (near CN14) 1
- (near CN14) DNF
- 5V_STLK OVERCURRENT PROTECTION MANAGEMENT
- (current limit: 550mA)
- (current limit: 1.66A)
- Power1.5.SNK
- PowerDefault.SNK
- T_PWR_SEL2/PD5
- Hi-Z
- T_PWR_SEL1/PD4
- 0
- (current limit: 3.2A)
- Power3.0.SNK
- Hi-Z = IO set in high impedance

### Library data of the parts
C110 = MCD-02372: Capacitor, MLCC, 2.2uF, 25V, X7R, +/-10%, 0805, T=1,25mm; Manufacturer_Part_Number: GRM21BR71E225KE11; Manufacturer: MURATA; Part_Preference: Recommended; Partial_Alternate_Internal_Part_Number: MCD-04185; Component_Country_Of_Origin: Japan°; ShowFields: YES; ID: 4478
C129 C169 = MCD-00099: Capacitor, MLCC, 10uF, 10V, X5R, +/-10%, 0603, T=0.8mm; Part_Preference: Recommended; Manufacturer: MURATA; Manufacturer_Part_Number: GRM188R61A106KE69; Partial_Alternate_Internal_Part_Number: MCD-03152; Order_Code_RS: 2494233; Component_Country_Of_Origin: Japan°°; ShowFields: YES; ID: 2770
C131 = MCD-00016: Capacitor, MLCC, 20pF, 50V, NPO, +/- 5%, 0402, T=0.5mm; Manufacturer_Part_Number: CC0402JRNPO9BN200; Manufacturer: YAGEO; Part_Preference: Recommended; Component_Country_Of_Origin: China; ShowFields: YES; ID: 2479
C132 C145 C160 = MCD-02606: Capacitor, MLCC, 2.2uF, 6.3V, X5R, +/-10%, 0402, T=0.5mm; Part_Preference: Recommended; Manufacturer: YAGEO; Manufacturer_Part_Number: CC0402KRX5R5BB225; Order_Code_RS: 1992205; ShowFields: YES; ID: 4712; Component_Country_Of_Origin: China°
C133 C140 = MCD-01774: Capacitor, MLCC, 2.7pF, 50V, NPO, +/-0.1pF, 0402, T=0.5mm; Part_Preference: Recommended; Manufacturer: YAGEO; Manufacturer_Part_Number: CC0402BRNPO9BN2R7; Component_Country_Of_Origin: China; ID: 3874; ShowFields: YES
C149 C281 C282 C289 C290 C297-C299 C303 C310 C311 C324-C329 C333 = MCD-00006: Capacitor, MLCC, 100nF, 16V, X7R, +/-10%, 0402, T=0.5mm; Manufacturer_Part_Number: CC0402KRX7R7BB104; Manufacturer: YAGEO; Part_Preference: Recommended; Partial_Alternate_Internal_Part_Number: MCD-03299; Order_Code_RS: 9402047; Component_Country_Of_Origin: China; ShowFields: YES; ID: 2474
C157 C158 C173 = MCD-02198: Capacitor, MLCC, 10nF, 50V, X7R, +/-10%, 0402, T=0.5mm; Part_Preference: Recommended; Manufacturer: YAGEO; Manufacturer_Part_Number: CC0402KRX7R9BB103; Order_Code_RS: 6169644; Component_Country_Of_Origin: China; ShowFields: YES; ID: 4298
C164 = MCD-00205: Capacitor, MLCC, 100pF, 50V, NPO, +/-5%, 0402, T=0.5mm; Part_Preference: Recommended; Manufacturer: YAGEO; Manufacturer_Part_Number: CC0402JRNPO9BN101; Component_Country_Of_Origin: China; ShowFields: YES; ID: 2658
C165 = MCD-00099: Capacitor, MLCC, 10uF, 10V, X5R, +/-10%, 0603, T=0.8mm; Part_Preference: Recommended; Manufacturer: MURATA; Manufacturer_Part_Number: GRM188R61A106KE69; Partial_Alternate_Internal_Part_Number: MCD-03152; Order_Code_RS: 2494233; Component_Country_Of_Origin: Japan°°; ID: 2770; ShowFields: YES
C166 C172 = MCD-02355: Capacitor, MLCC, 100nF, 25V, X7R, +/-10%, 0402, T=0.5mm; Part_Preference: Recommended; Manufacturer: WALSIN TECHNOLOGY CORPORATION; Manufacturer_Part_Number: 0402B104K250CT; Partial_Alternate_Internal_Part_Number: MCD-03302, MCD-03304; Order_Code_RS: 176-3114; Component_Country_Of_Origin: Unknown; ShowFields: YES; ID: 4461
C176 = MCD-03140: Capacitor, MLCC, 10uF, 6.3V, X5R, +/-20%, 0402, T=0.5mm; Part_Preference: Recommended; Manufacturer: MURATA; Manufacturer_Part_Number: GRM155R60J106ME05; Component_Country_Of_Origin: China, Japan; ShowFields: YES; ID: 5256
CN14 = MCD-00029: Header, 4x1, 2.54mm, VR, TH, T=5.84mm/2.54mm; Manufacturer_Part_Number: TSW-104-07-G-S; Manufacturer: SAMTEC; Part_Type: Connector; Part_Preference: Recommended; Partial_Alternate_Internal_Part_Number: MCD-04227; Order_Code_RS: 161-2460; Component_Country_Of_Origin: United States°; ShowFields: YES; ID: 2487
CN21 = MCD-03232: as CN15 on sheet USB_PCIe
D2 D3 = MCD-03011: Signal Schottky Diode, If=1A, Ifsm=5A, Vf =0.54V@1A, Vrrm=23V, Ir = 0.65µA@5V, SOD-323; Part_Preference: Recommended; Manufacturer: STMICROELECTRONICS; Order_Code_RS: 165-7545; ShowFields: YES; ID: 5127; Component_Country_Of_Origin: China
JP3 = MCD-00045: Header, 2x1, 2.54mm, VR, TH, T=5.84mm/2.54mm; Part_Preference: Recommended; Part_Type: Connector; Manufacturer: SAMTEC; Manufacturer_Part_Number: TSW-102-07-G-S; Alternate_Internal_Part_Number: MCD-02390; Partial_Alternate_Internal_Part_Number: MCD-02957, MCD-03720, MCD-03979, MCD-04249; Order_Code_RS: 2505044; Component_Country_Of_Origin: China, Costa Rica, Malaysia, USA, Vietnam; ShowFields: YES; ID: 2545
LD5 LD6 = MCD-02631: LED Bicolor, Green/Red, 2V, 20mA,  4-PLCC; Part_Type: Display; Part_Preference: Recommended; Manufacturer: WURTH ELEKTRONIK; Manufacturer_Part_Number: 150141SV73110; Partial_Alternate_Internal_Part_Number: MCD-02402; Order_Code_RS: 184-6963; Component_Country_Of_Origin: China; ShowFields: YES; ID: 4737
LNK13 = MCD-02777: Track link on PCB 200um width for layout routing. No component assembly and no component in BOM; Part_Type: Misc; Part_Preference: Recommended; ShowFields: YES; ID: 4889; Component_Country_Of_Origin: Unknown
R129 R154 R212 = MCD-00052: as R290 on sheet USB_PCIe
R130 R132 = MCD-00062: Resistor, 330R, 0402, +/-1%, 1/16W; Part_Preference: Recommended; Manufacturer: YAGEO; Manufacturer_Part_Number: RC0402FR-07330RL; Order_Code_RS: 9239170; Component_Country_Of_Origin: China; ShowFields: YES; ID: 2529
R131 R133 = MCD-02665: Resistor, 1K, 0402, +/-0.1%, 1/16W, +/-25ppm/°C; Part_Preference: Recommended; Manufacturer: YAGEO; Manufacturer_Part_Number: RT0402BRD071KL; Order_Code_RS: 199-1298; ShowFields: YES; ID: 4771; Component_Country_Of_Origin: Taiwan
R134 R153 R207 R209 = MCD-00455: Resistor, 33R, 0402, +/-1%, 1/16W; Part_Preference: Recommended; Manufacturer: YAGEO; Manufacturer_Part_Number: RC0402FR-0733RL; Component_Country_Of_Origin: China; ShowFields: YES; ID: 2821
R155 R211 = MCD-00052: Resistor, 0R, 0402, +/-5%, 1/16W; Manufacturer_Part_Number: RC0402JR-070RL; Manufacturer: YAGEO; Part_Preference: Recommended; Order_Code_RS: 9232516RL; Component_Country_Of_Origin: China; ShowFields: YES; ID: 2540
R156 R213-R215 = MCD-00053: Resistor, 10K, 0402, +/-1%, 1/16W; Manufacturer_Part_Number: RC0402FR-0710KL; Manufacturer: YAGEO; BMS_Part_Number: 9131590; Part_Preference: Recommended; Order_Code_RS: 9239359; Component_Country_Of_Origin: China; ShowFields: YES; ID: 2539
R181 = MCD-00067: Resistor, 100R, 0402, +/- 1%, 1/16W; Part_Preference: Recommended; Manufacturer: YAGEO; Manufacturer_Part_Number: RC0402FR-07100RL; Order_Code_RS: 9239111; Component_Country_Of_Origin: China; ShowFields: YES; ID: 2527
R194 = MCD-00185: Resistor, 3K, 0402, +/-1%, 1/16W; Manufacturer_Part_Number: RC0402FR-073KL; Manufacturer: YAGEO; Part_Preference: Recommended; Component_Country_Of_Origin: China; ShowFields: YES; ID: 2682
R216 R221 R222 = MCD-00333: Resistor, 5K1, 0402, +/-1%, 1/16W; Part_Preference: Recommended; Manufacturer: YAGEO; Manufacturer_Part_Number: RC0402FR-075K1L; Component_Country_Of_Origin: China; ShowFields: YES; ID: 2944
R217 R218 R227 R229 R239 = MCD-00059: Resistor, 100K, 0402, +/-1%, 1/16W; Manufacturer_Part_Number: RC0402FR-07100KL; Manufacturer: YAGEO; Part_Preference: Recommended; Partial_Alternate_Internal_Part_Number: MCD-03301; Order_Code_RS: 2421891; Component_Country_Of_Origin: China; ShowFields: YES; ID: 2533
R226 R230 = MCD-00063: Resistor,47K,0402,1%,1/16W; Manufacturer_Part_Number: RC0402FR-0747KL; Manufacturer: YAGEO; Part_Preference: Recommended; ECCN_US: EAR99; ECCN_EU: NEC; Provided_By: SUBCO; Order_Code_RS: 9239430; Component_Country_Of_Origin: China; ID: 2528; ShowFields: YES
R240 = MCD-00381: Resistor, 1K3, 0402, +/-1%, 1/16W; Part_Preference: Recommended; Manufacturer: YAGEO; Manufacturer_Part_Number: RC0402FR-071K3L; Component_Country_Of_Origin: China; ShowFields: YES; ID: 2898
R241 = MCD-00409: Resistor, 1K8, 0402, +/-1%, 1/16W; Part_Preference: Recommended; Manufacturer: YAGEO; Manufacturer_Part_Number: RC0402FR-071K8L; Component_Country_Of_Origin: China; ShowFields: YES; ID: 2871
R242 = MCD-02455: Resistor, 3K9, 0402, +/-1%, 1/16W, +/-100ppm/°C; Part_Preference: Recommended; Manufacturer: YAGEO; Manufacturer_Part_Number: RC0402FR-073K9L; Order_Code_RS: 198-7783; Component_Country_Of_Origin: China; ShowFields: YES; ID: 4561
TP26-TP29 = MCD-00074: as TP14-TP21 on sheet USB_PCIe
TP33 = MCD-00074: Test Point 1mm; Part_Type: Misc; Part_Preference: Recommended; ShowFields: YES; ID: 2518; Component_Country_Of_Origin: Unknown
U35 = MCD-02514: LDO, 3.3V, 300mA, High input voltage: 2.5V to 28V, SOT23-5L; Part_Type: IC; Part_Preference: Recommended; Manufacturer: STMICROELECTRONICS; Component_Country_Of_Origin: Malaysia; ShowFields: YES; ID: 4620
U36 = MCD-02706: MCU, Arm Cortex-M7 32-bit MCU, 512KB Flash, 276KB RAM, With Crypto; BMS_Part_Number: 9175300; Part_Type: IC; Part_Preference: Not recommended; Manufacturer: STMICROELECTRONICS; Manufacturer_HQ_COO: EU; Order_Code_RS: 135-8241; ShowFields: YES; ID: 4812; Component_Country_Of_Origin: Philippines
U47 = MCD-00649: Common mode filter with ESD protection for USB 2.0 interface; Part_Type: Diode; Manufacturer: STMICROELECTRONICS; BMS_Part_Number: 9151138; Part_Preference: Recommended; Manufacturer_HQ_COO: EU; Component_Country_Of_Origin: China; ShowFields: YES; ID: 3094; Order_Code_RS: 880-5276
U48 = MCD-01207: High power Transient voltage suppressor:25V/35A EOS and ESD transients protection.; Part_Type: Diode; Manufacturer: STMICROELECTRONICS; BMS_Part_Number: 9179045; Part_Preference: Recommended; Manufacturer_HQ_COO: EU; Component_Country_Of_Origin: China; ShowFields: YES; ID: 3289; Order_Code_RS: 163-9774
U49 = MCD-00159: 500mA, Enhanced single channel power switches with active high enable pin; Part_Type: IC; Manufacturer: STMICROELECTRONICS; Alternate_Manufacturer_Part_Number: TPS2051C; Alternate_Manufacturer: TEXAS INSTRUMENTS; BMS_Part_Number: 9159009; Part_Preference: Recommended; Provided_By: Subcon; Initial_Board_Reference: MB1264; Component_Country_Of_Origin: Malaysia; ID: 2708; Order_Code_RS: 165-5516; ShowFields: YES
U52 = MCD-02532: IC, eFuse with Fast Overvoltage Protection 2.7V to 18V 4A 34mOhm 8-Pin WSON; Part_Preference: Recommended; Manufacturer: TEXAS INSTRUMENTS; ShowFields: YES; ID: 4638; Component_Country_Of_Origin: Thailand
X7 = MCD-01036: Crystal, 24MHz, 6pF, +/-20ppm, 80R, 2x1.6mm; BMS_Part_Number: 9157045; Part_Type: Crystal_Osc; Part_Preference: Recommended; Manufacturer: NDK; Manufacturer_Part_Number: NX2016SA-24MHZ-EXS00A-CS10820; Component_Country_Of_Origin: Japan; ID: 2989; ShowFields: YES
